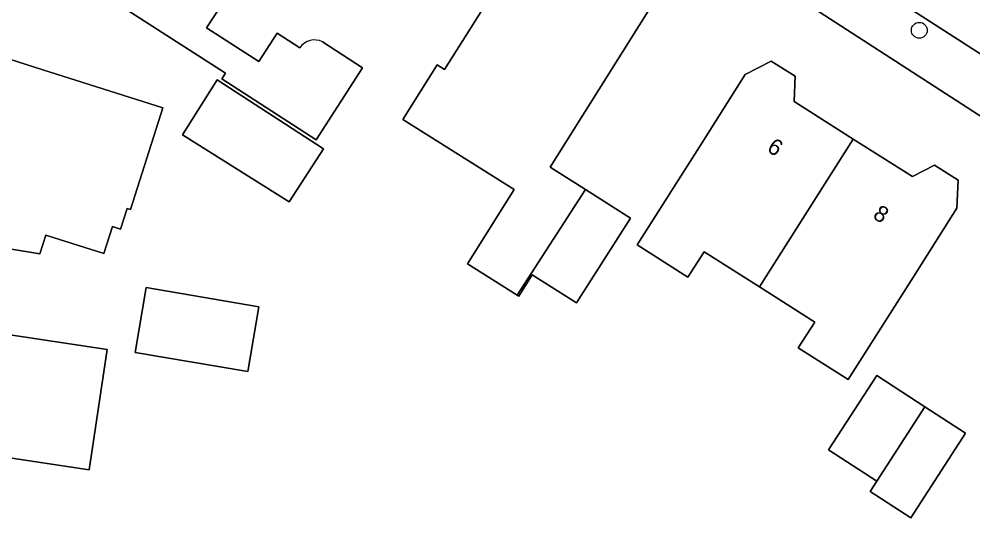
# Model space of a CAD drawing. Extents: x 161139 to 161601, y 381708 to 382245.
# Drawn here: x 161296.5 to 161355.3, y 382017.4 to 382048.2 of the extents above; entities that cross this region are included whole.
import ezdxf

# ---------------------------------------------------------------- set-up
doc = ezdxf.new("R2010")
doc.units = 0
for name, color, linetype in [('IMGEO_Boom', 7, 'Continuous'), ('IMGEO_Erf', 7, 'Continuous'), ('IMGEO_Pand', 7, 'Continuous'), ('IMGEO_Pand_nummerreeks', 7, 'Continuous'), ('IMGEO_Rijbaan_lokaal_open', 7, 'Continuous'), ('IMGEO_Voetpad_open', 7, 'Continuous')]:
    doc.layers.add(name, color=color, linetype=linetype)

msp = doc.modelspace()

# ---------------------------------------------------------------- linework, layer by layer
at = {"layer": 'IMGEO_Boom'}
msp.add_circle((161352.004, 382047.471), 0.489, dxfattribs=at)
at = {"layer": 'IMGEO_Erf'}
for points in [[(161421.048, 382000), (161306.066, 382074.349)], [(161302.036, 382049.498), (161302.677, 382050.489), (161300.358, 382051.989), (161303.045, 382056.146), (161298.669, 382058.976), (161305.221, 382069.111), (161309.823, 382066.136), (161309.493, 382065.626), (161313.942, 382062.75), (161311.764, 382059.381), (161309.556, 382060.808), (161305.969, 382055.257), (161305.428, 382055.607), (161304.454, 382054.101), (161309.98, 382050.528), (161308.099, 382047.617), (161311.312, 382045.54), (161312.444, 382047.29), (161313.843, 382046.386)], [(161315.233, 382046.758), (161317.706, 382045.158), (161314.844, 382040.73), (161309.038, 382044.479), (161309.262, 382044.827), (161302.036, 382049.498)]]:
    msp.add_lwpolyline(points, dxfattribs=at)
for points in [[(161330.891, 382030.671), (161328.144, 382032.397), (161327.326, 382031.094), (161327.227, 382031.156), (161324.172, 382033.077), (161327.053, 382037.661), (161320.18, 382041.981), (161322.293, 382045.342), (161322.758, 382045.049), (161325.756, 382049.819), (161328.417, 382054.052), (161329.525, 382053.356), (161330.221, 382053.724), (161332.458, 382052.318), (161332.427, 382051.481), (161335.761, 382049.386), (161329.259, 382039.042), (161331.435, 382037.66), (161334.21, 382035.898)], [(161303.197, 382036.497), (161302.791, 382035.219), (161302.289, 382035.386), (161301.757, 382033.71), (161298.19, 382034.841), (161297.826, 382033.694), (161294.062, 382034.318), (161294.942, 382037.087), (161290.672, 382038.443), (161293.249, 382046.556), (161298.015, 382045.043), (161305.396, 382042.699), (161303.406, 382036.431)], [(161347.618, 382025.948), (161344.549, 382027.897), (161345.564, 382029.496), (161342.157, 382031.659), (161338.744, 382033.826), (161337.751, 382032.263), (161334.62, 382034.25), (161338.601, 382040.519), (161341.281, 382044.739), (161342.875, 382045.571), (161344.352, 382044.634), (161344.286, 382043.087), (161347.935, 382040.77), (161351.583, 382038.453), (161352.931, 382039.157), (161354.394, 382038.228), (161354.321, 382036.501), (161351.641, 382032.281)], [(161306.609, 382041.036), (161308.737, 382044.423), (161315.296, 382040.174), (161313.181, 382036.907)], [(161310.629, 382026.444), (161303.689, 382027.624), (161304.368, 382031.618), (161311.308, 382030.438)], [(161290.014, 382021.115), (161290.153, 382022.036), (161287.554, 382022.426), (161287.686, 382023.3), (161287.362, 382023.349), (161287.957, 382027.313), (161288.335, 382027.257), (161288.717, 382029.8), (161293.662, 382029.057), (161301.968, 382027.808), (161300.853, 382020.383), (161292.13, 382021.693), (161292.068, 382021.281), (161290.868, 382021.462), (161290.798, 382020.998)], [(161351.48, 382017.438), (161348.971, 382019.06), (161349.384, 382019.699), (161346.418, 382021.618), (161349.381, 382026.197), (161352.347, 382024.278), (161354.854, 382022.657)]]:
    msp.add_lwpolyline(points, close=True, dxfattribs=at)
msp.add_arc((161314.743, 382045.806), 1.07, 62.74834, 147.21709, dxfattribs=at)
at = {"layer": 'IMGEO_Pand'}
for points in [[(161313.942, 382062.75), (161309.493, 382065.626), (161309.823, 382066.136), (161305.221, 382069.111), (161298.669, 382058.976), (161303.045, 382056.146), (161300.358, 382051.989), (161302.677, 382050.489), (161302.036, 382049.498), (161309.262, 382044.827), (161309.038, 382044.479), (161314.844, 382040.73), (161317.706, 382045.158), (161315.233, 382046.758)], [(161313.843, 382046.386), (161312.444, 382047.29), (161311.312, 382045.54), (161308.099, 382047.617), (161309.98, 382050.528), (161304.454, 382054.101), (161305.428, 382055.607), (161305.969, 382055.257), (161309.556, 382060.808), (161311.764, 382059.381), (161313.942, 382062.75)]]:
    msp.add_lwpolyline(points, dxfattribs=at)
for points in [[(161327.227, 382031.156), (161331.435, 382037.66), (161329.259, 382039.042), (161335.761, 382049.386), (161332.427, 382051.481), (161332.458, 382052.318), (161330.221, 382053.724), (161329.525, 382053.356), (161328.417, 382054.052), (161325.756, 382049.819), (161322.758, 382045.049), (161322.293, 382045.342), (161320.18, 382041.981), (161327.053, 382037.661), (161324.172, 382033.077)], [(161305.396, 382042.699), (161298.015, 382045.043), (161293.249, 382046.556), (161290.672, 382038.443), (161294.942, 382037.087), (161294.062, 382034.318), (161297.826, 382033.694), (161298.19, 382034.841), (161301.757, 382033.71), (161302.289, 382035.386), (161302.791, 382035.219), (161303.197, 382036.497), (161303.406, 382036.431)], [(161342.157, 382031.659), (161347.935, 382040.77), (161344.286, 382043.087), (161344.352, 382044.634), (161342.875, 382045.571), (161341.281, 382044.739), (161338.601, 382040.519), (161334.62, 382034.25), (161337.751, 382032.263), (161338.744, 382033.826)], [(161308.737, 382044.423), (161306.609, 382041.036), (161313.181, 382036.907), (161315.296, 382040.174)], [(161342.157, 382031.659), (161345.564, 382029.496), (161344.549, 382027.897), (161347.618, 382025.948), (161351.641, 382032.281), (161354.321, 382036.501), (161354.394, 382038.228), (161352.931, 382039.157), (161351.583, 382038.453), (161347.935, 382040.77)], [(161327.227, 382031.156), (161327.326, 382031.094), (161328.144, 382032.397), (161330.891, 382030.671), (161334.21, 382035.898), (161331.435, 382037.66)], [(161310.629, 382026.444), (161311.308, 382030.438), (161304.368, 382031.618), (161303.689, 382027.624)], [(161290.798, 382020.998), (161290.868, 382021.462), (161292.068, 382021.281), (161292.13, 382021.693), (161300.853, 382020.383), (161301.968, 382027.808), (161293.662, 382029.057), (161288.717, 382029.8), (161288.335, 382027.257), (161287.957, 382027.313), (161287.362, 382023.349), (161287.686, 382023.3), (161287.554, 382022.426), (161290.153, 382022.036), (161290.014, 382021.115)], [(161352.347, 382024.278), (161349.381, 382026.197), (161346.418, 382021.618), (161349.384, 382019.699)], [(161352.347, 382024.278), (161349.384, 382019.699), (161348.971, 382019.06), (161351.48, 382017.438), (161354.854, 382022.657)]]:
    msp.add_lwpolyline(points, close=True, dxfattribs=at)
msp.add_arc((161314.743, 382045.806), 1.07, 62.74834, 147.21709, dxfattribs=at)
at = {"layer": 'IMGEO_Rijbaan_lokaal_open'}
msp.add_lwpolyline([(161375.585, 382040.285), (161362.411, 382048.813), (161356.674, 382052.498), (161311.536, 382081.664), (161306.338, 382077.878), (161325.321, 382065.668), (161328.504, 382063.628), (161339.032, 382056.795), (161345.442, 382052.667), (161359.944, 382043.32), (161366.307, 382039.161), (161381.679, 382029.228), (161388.068, 382025.069), (161398.439, 382018.395)], dxfattribs=at)
at = {"layer": 'IMGEO_Voetpad_open'}
for points in [[(161398.439, 382018.395), (161388.068, 382025.069), (161381.679, 382029.228), (161366.307, 382039.161), (161359.944, 382043.32), (161345.442, 382052.667), (161339.032, 382056.795), (161328.504, 382063.628), (161325.321, 382065.668), (161306.338, 382077.878), (161302.036, 382073.583), (161301.893, 382073.339)], [(161306.066, 382074.349), (161421.048, 382000), (161474.804, 381965.241), (161478.068, 381963.057), (161478.909, 381962.515)]]:
    msp.add_lwpolyline(points, dxfattribs=at)

# ---------------------------------------------------------------- texts
at = {"layer": 'IMGEO_Pand_nummerreeks'}
for s, p in [('6', (161342.557, 382040.054)), ('8', (161349.08, 382035.933))]:
    msp.add_text(s, height=1, rotation=327.71741, dxfattribs=at).set_placement(p)

doc.saveas('drawing.dxf')
